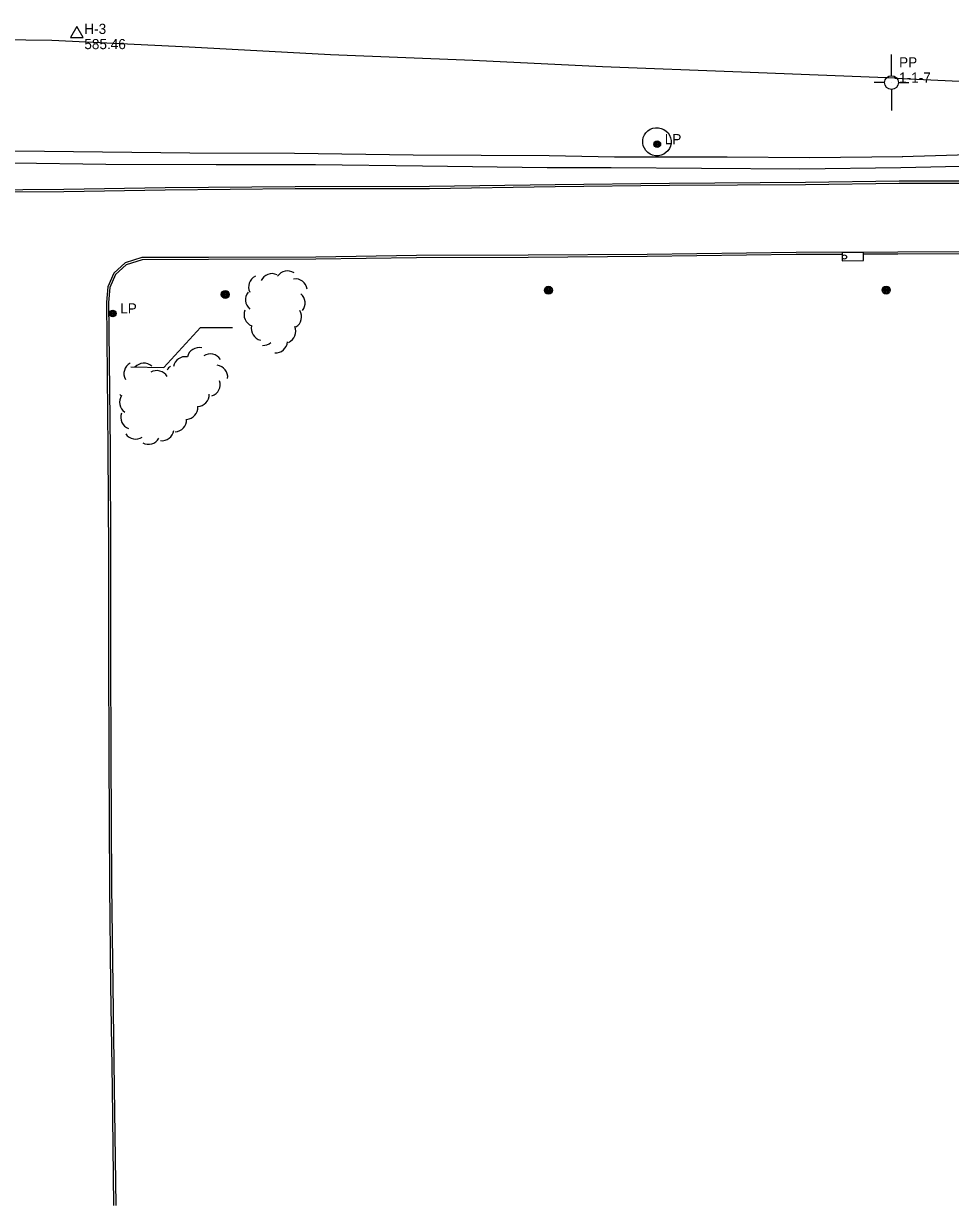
# Model space of a CAD drawing. Extents: x 2402803 to 2427059, y 6985292 to 6997652.
# Drawn here: x 2407177 to 2407615, y 6990725 to 6991283 of the extents above; entities that cross this region are included whole.
import ezdxf

# ---------------------------------------------------------------- set-up
doc = ezdxf.new("R2010")
doc.units = 0
for name, color, linetype in [('p_control ground ctrl', 7, 'Continuous'), ('p_drainage conc drain', 7, 'Continuous'), ('p_road - paved curb', 7, 'Continuous'), ('p_road bridge end', 7, 'Continuous'), ('p_structure general', 7, 'Continuous'), ('p_structure slab', 7, 'Continuous'), ('p_utility manhole', 7, 'Continuous'), ('p_veg woods', 7, 'Continuous'), ('V7 LEVEL 31', 7, 'Continuous')]:
    doc.layers.add(name, color=color, linetype=linetype)

msp = doc.modelspace()

# ---------------------------------------------------------------- linework, layer by layer
at = {"layer": 'p_control ground ctrl'}
for p, q in [((2407202.24, 6991282.08), (2407199.24, 6991276.88)), ((2407205.24, 6991276.88), (2407202.24, 6991282.08)), ((2407199.24, 6991276.88), (2407205.24, 6991276.88)), ((2407202.24, 6991278.6), (2407202.24, 6991278.64)), ((2407587.5, 6991258.83), (2407587.52, 6991268.83)), ((2407584.26, 6991255.59), (2407579.26, 6991255.6)), ((2407587.5, 6991255.59), (2407587.5, 6991255.63)), ((2407590.74, 6991255.59), (2407595.74, 6991255.58)), ((2407587.5, 6991252.35), (2407587.48, 6991242.35))]:
    msp.add_line(p, q, dxfattribs=at)
msp.add_circle((2407587.5, 6991255.59), 3.24, dxfattribs=at)
at = {"layer": 'p_drainage conc drain'}
for points in [[(2407592.57, 6991220.6), (2407650.18, 6991222.34), (2407706.48, 6991223.71), (2407750.94, 6991225.4), (2407790.57, 6991227.22), (2407790.72, 6991224.8), (2407790.74, 6991221.87), (2407751.9, 6991220.08), (2407701.01, 6991217.97), (2407666.97, 6991217.3), (2407627.29, 6991216.13), (2407591.95, 6991215.31)], [(2407001.18, 6991221.72), (2407000.84, 6991224.35), (2407052.45, 6991224.16), (2407121.85, 6991223.84), (2407187.04, 6991223.17), (2407255.69, 6991222.44), (2407305.2, 6991222.26), (2407361.35, 6991221.36), (2407425.66, 6991221.16), (2407456.59, 6991220.43), (2407509.77, 6991220.52), (2407548.75, 6991220.15), (2407592.87, 6991220.6)], [(2407591.95, 6991215.31), (2407544.21, 6991214.6), (2407497.63, 6991215.02), (2407454.95, 6991215.28), (2407424.72, 6991215.2), (2407365.74, 6991216.06), (2407315.13, 6991216.76), (2407268.08, 6991216.64), (2407215.93, 6991216.8), (2407172.31, 6991217.46), (2407118.11, 6991218.05), (2407071.37, 6991218.47), (2407026.77, 6991218.95), (2407001.1, 6991218.2), (2407000.94, 6991221.77), (2407000.84, 6991224.35)]]:
    msp.add_lwpolyline(points, dxfattribs=at)
at = {"layer": 'p_road - paved curb'}
for points in [[(2407589.11, 6991257.67), (2407516.5, 6991260.5), (2407450.86, 6991262.99), (2407389.48, 6991265.97), (2407322.16, 6991268.67), (2407255.33, 6991272.41), (2407190.47, 6991275.46), (2407128.56, 6991276.24), (2407076.8, 6991275.71), (2407025.1, 6991276.06), (2406967.36, 6991275.51), (2406913.56, 6991275.47), (2406848.41, 6991274.6), (2406789.73, 6991274.6), (2406724.1, 6991273.89), (2406649.67, 6991273.21), (2406587.96, 6991272.87), (2406532.89, 6991272.66), (2406485.46, 6991271.79), (2406462.22, 6991270.92), (2406448.87, 6991267.03), (2406438.89, 6991260.72), (2406431.55, 6991250.74), (2406427, 6991235.97)], [(2407589.11, 6991257.67), (2407687.65, 6991253.12), (2407773.82, 6991250.4), (2407861.51, 6991250.15), (2407953.2, 6991250.12), (2408031.39, 6991250.82), (2408040.57, 6991250.89)], [(2407591.12, 6991209.07), (2407653.81, 6991209.06), (2407716.28, 6991209.69), (2407786.28, 6991210.59), (2407846.63, 6991210.95), (2407920.32, 6991211.47), (2407982.2, 6991212.21), (2408035.34, 6991212.64)], [(2407591.12, 6991208.07), (2407653.81, 6991208.06), (2407716.29, 6991208.69), (2407786.29, 6991209.59), (2407846.64, 6991209.95), (2407920.33, 6991210.47), (2407982.21, 6991211.21), (2408035.4, 6991211.64)], [(2407137.96, 6991204.72), (2407196.05, 6991205.13), (2407244.03, 6991205.93), (2407305.55, 6991206.43), (2407368.98, 6991206.54), (2407428.45, 6991207.42), (2407482.45, 6991208.08), (2407546.78, 6991208.41), (2407591.11, 6991209.07)], [(2407137.97, 6991203.72), (2407196.06, 6991204.13), (2407244.04, 6991204.93), (2407305.55, 6991205.43), (2407368.99, 6991205.54), (2407428.46, 6991206.42), (2407482.46, 6991207.08), (2407546.79, 6991207.41), (2407591.12, 6991208.07)], [(2407891.5, 6991174.78), (2407883.05, 6991176.54), (2407872.13, 6991177.69), (2407831.02, 6991176.97), (2407778.81, 6991176.84), (2407735.01, 6991176.85), (2407690.01, 6991176.47), (2407633.93, 6991175.53), (2407590.57, 6991175.43)], [(2407891.3, 6991173.8), (2407882.9, 6991175.55), (2407872.09, 6991176.69), (2407831.03, 6991175.97), (2407778.81, 6991175.84), (2407735.01, 6991175.85), (2407690.02, 6991175.47), (2407633.94, 6991174.53), (2407590.57, 6991174.43)], [(2407590.57, 6991175.43), (2407542.4, 6991175.25), (2407471.92, 6991174.27), (2407415.73, 6991173.88), (2407362.83, 6991173.77), (2407315.3, 6991173.06), (2407264.6, 6991172.93), (2407233.06, 6991172.8), (2407225.16, 6991170.33), (2407219.71, 6991165.39), (2407216.88, 6991158.96), (2407216.24, 6991151.66), (2407216.98, 6991082.33), (2407217.2, 6991032.82), (2407217.2, 6990983.93), (2407217.38, 6990937.04), (2407217.71, 6990875.56), (2407218.21, 6990828.56), (2407218.9, 6990780.13), (2407219.67, 6990724.52)], [(2407563.94, 6991174.33), (2407542.41, 6991174.25), (2407471.93, 6991173.27), (2407415.73, 6991172.88), (2407362.84, 6991172.77), (2407315.31, 6991172.06), (2407264.6, 6991171.93), (2407233.21, 6991171.8), (2407225.67, 6991169.44), (2407220.54, 6991164.79), (2407217.86, 6991158.71), (2407217.24, 6991151.62), (2407217.98, 6991082.34), (2407218.2, 6991032.82), (2407218.2, 6990983.93), (2407218.38, 6990937.04), (2407218.71, 6990875.57), (2407219.21, 6990828.57), (2407219.9, 6990780.14), (2407220.67, 6990724.53)], [(2407590.57, 6991174.43), (2407574.27, 6991174.37)]]:
    msp.add_lwpolyline(points, dxfattribs=at)
at = {"layer": 'p_road bridge end'}
msp.add_lwpolyline([(2407574.2, 6991175.27), (2407564.2, 6991175.23), (2407564.21, 6991171.33), (2407574.21, 6991171.37)], close=True, dxfattribs=at)
at = {"layer": 'p_structure general'}
msp.add_lwpolyline([(2407227.78, 6991121.13), (2407243.48, 6991120.77), (2407260.74, 6991139.73), (2407275.83, 6991139.68)], dxfattribs=at)
msp.add_circle((2407565.27, 6991173.09), 1, dxfattribs=at)
at = {"layer": 'p_structure slab'}
msp.add_ellipse((2407476.6, 6991227.61), major_axis=(6.73, -0.71), ratio=0.980368, dxfattribs=at)
at = {"layer": 'p_utility manhole'}
for centre, radius in [((2407476.72, 6991226.45), 1.6), ((2407476.72, 6991226.45), 1.3), ((2407476.72, 6991226.45), 1), ((2407476.72, 6991226.45), 0.539), ((2407476.72, 6991226.45), 0.192), ((2407425.29, 6991157.36), 1.9), ((2407584.98, 6991157.46), 1.9), ((2407272.44, 6991155.36), 1.9), ((2407272.44, 6991155.36), 1.44), ((2407272.44, 6991155.36), 0.973), ((2407272.44, 6991155.36), 0.539), ((2407272.44, 6991155.36), 0.192), ((2407425.29, 6991157.36), 1.44), ((2407425.29, 6991157.36), 0.973), ((2407425.29, 6991157.36), 0.539), ((2407425.29, 6991157.36), 0.192), ((2407584.98, 6991157.46), 1.44), ((2407584.98, 6991157.46), 0.973), ((2407584.98, 6991157.46), 0.539), ((2407584.98, 6991157.46), 0.192), ((2407219.21, 6991146.37), 1.6), ((2407219.21, 6991146.37), 1.3), ((2407219.21, 6991146.37), 1), ((2407219.21, 6991146.37), 0.539), ((2407219.21, 6991146.37), 0.192)]:
    msp.add_circle(centre, radius, dxfattribs=at)
at = {"layer": 'p_veg woods'}
for centre, start, end in [((2407294.53, 6991159.57), 64.6108, 154.6108), ((2407301.89, 6991160.9), 56.7211, 146.7211), ((2407289.15, 6991158.88), 115.756, 205.756), ((2407305.64, 6991157.07), 8.6931, 98.6931), ((2407287.62, 6991152.86), 140.6214, 230.6214), ((2407304.58, 6991151.34), 320.3819, 50.3819), ((2407286.97, 6991145.86), 159.0848, 249.0848), ((2407302.9, 6991144.82), 301.3224, 31.3224), ((2407290.41, 6991139.25), 166.6585, 256.6585), ((2407300.11, 6991137.91), 293.3566, 23.3566), ((2407290.32, 6991136.93), 267.2112, 311.3086), ((2407296.19, 6991133.33), 266.5779, 356.5779), ((2407253.5, 6991120.29), 79.3966, 169.3966), ((2407260.06, 6991124.56), 76.9686, 166.9686), ((2407265.39, 6991121.6), 32.7701, 122.7701), ((2407230.18, 6991117.87), 118.5932, 208.5932), ((2407234.02, 6991117.22), 48.9526, 138.9526), ((2407249.87, 6991116.85), 125.8476, 150.4494), ((2407267.98, 6991116.25), 352.9528, 82.9528), ((2407240.07, 6991113.7), 30.241, 120.241), ((2407264.4, 6991112.73), 288.284, 18.284), ((2407228.1, 6991104.38), 146.1514, 236.1514), ((2407226.41, 6991112.23), 227.0845, 236.5857), ((2407259.22, 6991108.06), 271.5544, 1.5544), ((2407228.7, 6991097.23), 159.8724, 249.8724), ((2407253.83, 6991101.92), 273.9534, 3.9534), ((2407248.53, 6991096.1), 272.1568, 2.1568), ((2407230.06, 6991092.59), 214.1715, 304.1715), ((2407236.17, 6991090.12), 241.0258, 331.0258), ((2407242.55, 6991091.85), 262.0863, 352.0863)]:
    msp.add_arc(centre, 5.65, start, end, dxfattribs=at)

# ---------------------------------------------------------------- texts
at = {"layer": 'p_control ground ctrl'}
for s, p in [('  H-3', (2407202.24, 6991278.6)), ('  PP', (2407587.52, 6991262.76)), ('  1-1-7', (2407587.52, 6991255.56))]:
    msp.add_text(s, height=4.8, dxfattribs=at).set_placement(p)
at = {"layer": 'p_utility manhole'}
for p in [(2407476.72, 6991226.45), (2407219.21, 6991146.37)]:
    msp.add_text('  LP', height=4.8, dxfattribs=at).set_placement(p)
at = {"layer": 'V7 LEVEL 31'}
msp.add_text('  585.46', height=4.8, dxfattribs=at).set_placement((2407202.24, 6991271.4))

doc.saveas('drawing.dxf')
